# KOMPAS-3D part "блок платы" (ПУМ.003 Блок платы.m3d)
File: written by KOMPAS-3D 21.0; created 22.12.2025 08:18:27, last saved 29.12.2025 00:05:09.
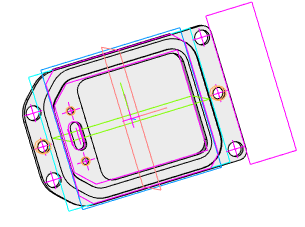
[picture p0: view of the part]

Document properties: Полное имя файла: C:\Users\Гузель\Desktop\ПУМ\ПУМ.003 Блок платы.m3d; Автор: User

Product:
- Part/product: блок платы
    Материал: Фторопласт-4  ГОСТ 10007-80 Е (density 2200 kg/m3)
    Масса: 0.031082
    Форматы листов документа: 2xA4@4~2
  - Body: Тело 6
      Масса: 0.03115
  - Body: Тело 1
      Масса: 0.03115

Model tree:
1. Эскиз:1
2. Элемент выдавливания:1
     Расстояние 2 = 1.5
3. Скругление:1  (with: Элемент выдавливания:1)
     Радиус = 4
4. Эскиз:2  (with: Элемент выдавливания:1, Скругление:1)
5. Элемент выдавливания:3  (with: Элемент выдавливания:1)
     Толщина стенки 1 = 1.5; Расстояние 1 = 8; Расстояние 2 = 1.5
6. Элемент выдавливания:4  (with: Элемент выдавливания:3)
     Толщина стенки 1 = 3.5; Расстояние 1 = 7.65
7. Элемент выдавливания:5  (with: Элемент выдавливания:4, Элемент выдавливания:3)
     Расстояние 1 = 9.5
8. Смещенная плоскость:1  (with: Элемент выдавливания:1)
     Расстояние = 4
9. Эскиз:3  (with: Элемент выдавливания:5)
10. Элемент выдавливания:6  (with: Элемент выдавливания:5)
     Расстояние 1 = 5.5
11. Эскиз:4  (with: Элемент выдавливания:6, Элемент выдавливания:1)
12. Элемент выдавливания:7  (with: Элемент выдавливания:1)
     Расстояние 1 = 4
13. Эскиз:5  (with: Элемент выдавливания:6, Элемент выдавливания:5, Элемент выдавливания:7)
14. Элемент выдавливания:8
     Расстояние 1 = 10
15. Элемент выдавливания:9  (with: Элемент выдавливания:7)
     Расстояние 2 = 2.5
16. Эскиз:6  (with: Элемент выдавливания:6)
17. Элемент выдавливания:10
     Расстояние 1 = 10; Расстояние 2 = 10
18. Скругление:2  (with: Элемент выдавливания:10)
     Радиус = 3
19. Эскиз:7  (with: Элемент выдавливания:9, Элемент выдавливания:3)
20. Элемент выдавливания:11  (with: Элемент выдавливания:3)
     Расстояние 1 = 8
21. Скругление:3  (with: Элемент выдавливания:11)
     Радиус = 4
22. Эскиз:8  (with: Элемент выдавливания:5, Элемент выдавливания:1)
23. Эскиз:9
24. Элемент выдавливания:12
     Расстояние 2 = 20
25. Фаска:2  (with: Элемент выдавливания:6)
     Угол = 45; Длина 1 = 10; Длина 2 = 10
26. Скругление:4  (with: Фаска:2)
     Радиус = 10
27. Зеркальный массив:1
28. Экземпляр ( 1 )
29. Экземпляр ( 2 )  (with: Элемент выдавливания:12)
30. сквозное  (with: Элемент выдавливания:5, Элемент выдавливания:10)
     Глубина выреза = 40; Диаметр отверстия = 5.2; Угол конуса дна = 118; Дно = 1; Расстояние 1 = 4; Расстояние 2 = 3.5; Длина резьбы = 10; Шаг резьбы = 0.5
31. Массив по точкам:1
32. Экземпляр ( 3 )  (with: сквозное, Эскиз:6, Экземпляр ( 1 ), Экземпляр ( 2 ))
33. Отверстие:3  (with: Элемент выдавливания:6, Фаска:2)  (labels: M5)
     Глубина выреза = 7; Диаметр отверстия = 4.13397; Угол конуса дна = 118; Расстояние 1 = 12.3744; Расстояние 2 = 3.5
34. M5  (with: Элемент выдавливания:6, Элемент выдавливания:5)  (labels: M5; cil0_24705-2004 coarse)
     Длина резьбы = 6; Шаг резьбы = 0.8; Номинальный диаметр резьбы = 5
35. Массив по точкам:2  (with: Экземпляр ( 1 ), Отверстие:3, Эскиз:6)  (labels: M5)
36. Скругление:5  (with: Элемент выдавливания:10)
     Радиус = 3
37. Эскиз:10  (with: Элемент выдавливания:6)
38. Элемент выдавливания:16  (with: Элемент выдавливания:1)
     Расстояние 1 = 3
39. Эскиз:11  (with: Элемент выдавливания:3, Элемент выдавливания:11)
40. Отверстие:4  (with: Элемент выдавливания:3)  (labels: M3)
     Глубина выреза = 3; Диаметр отверстия = 2.45873; Угол конуса дна = 118; Расстояние 1 = 5.5; Расстояние 2 = 6.44975
41. M3  (with: Элемент выдавливания:3)  (labels: M3; cil0_24705-2004 coarse)
     Длина резьбы = 2; Шаг резьбы = 0.5; Номинальный диаметр резьбы = 3
42. Отв-я под фиксацию платы  (with: Экземпляр ( 1 ), Отверстие:4)  (labels: M3)
43. Фаска:3  (with: Элемент выдавливания:7, Элемент выдавливания:5, Элемент выдавливания:8)  (labels: Фторопласт-4  ГОСТ 10007-80 Е)
     Угол = 45; Длина 1 = 0.5; Длина 2 = 0.5

Expressions: v688/2
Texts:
  Точка начала. Х
  Точка начала. Y
  Точка начала. Z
